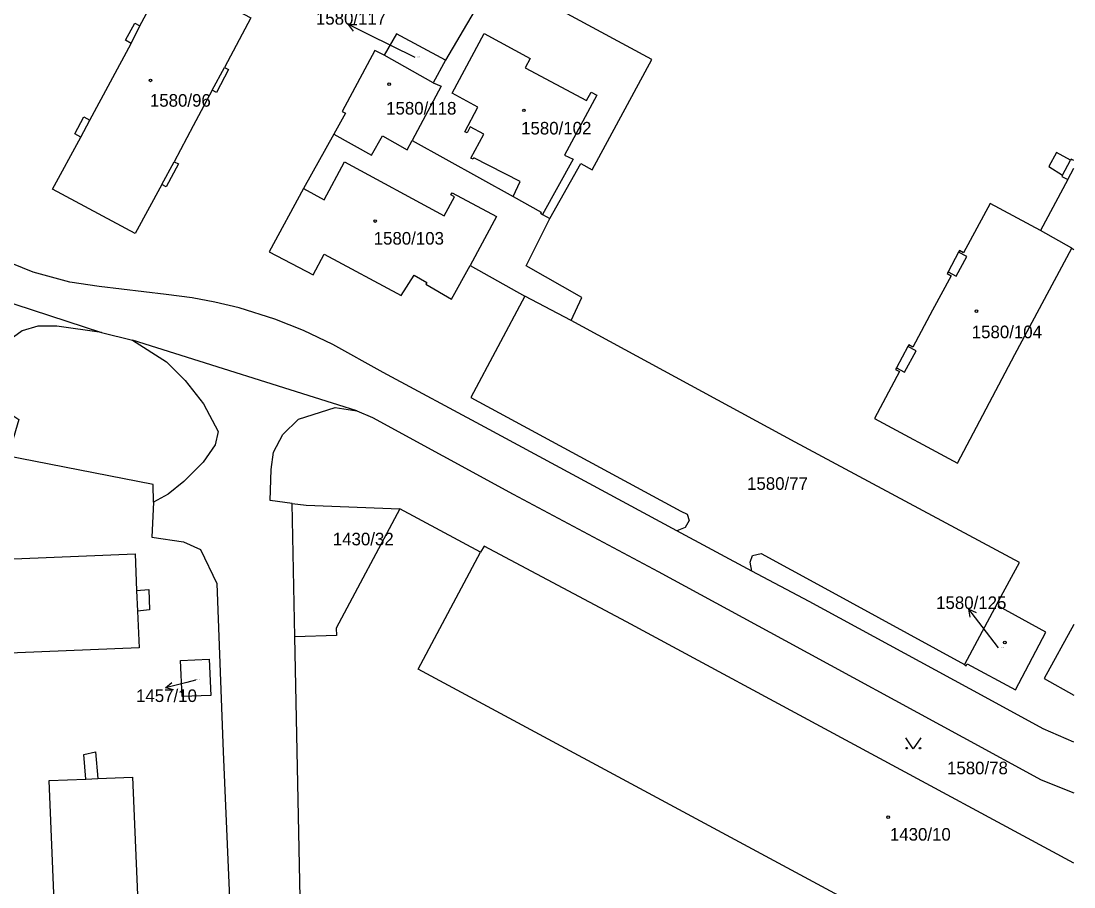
# Model space of a CAD drawing. Extents: x -736397 to -735924, y -1118983 to -1118245.
# Drawn here: x -736070.2 to -735928, y -1118454.8 to -1118338 of the extents above; entities that cross this region are included whole.
import ezdxf

# ---------------------------------------------------------------- set-up
doc = ezdxf.new("R2010")
doc.units = 0
for name, color, linetype in [('Vrstva 1', 7, 'Continuous'), ('Vrstva 16', 7, 'Continuous'), ('Vrstva 18', 7, 'Continuous'), ('Vrstva 19', 7, 'Continuous'), ('Vrstva 25', 7, 'Continuous'), ('Vrstva 4', 7, 'Continuous')]:
    doc.layers.add(name, color=color, linetype=linetype)

msp = doc.modelspace()

# ---------------------------------------------------------------- linework, layer by layer
at = {"layer": 'Vrstva 1'}
for p, q in [((-736014.55, -1118346.3), (-736021.15, -1118342.55)), ((-736012.85, -1118343.25), (-736014.55, -1118346.3)), ((-736027.93, -1118353.21), (-736032.05, -1118360.56)), ((-736017.37, -1118354.1), (-736003.75, -1118361.65)), ((-735928.88, -1118359.35), (-735932.57, -1118366.22)), ((-735999.77, -1118364.06), (-735998.8, -1118364.6)), ((-735928.33, -1118368.63), (-735932.57, -1118366.22)), ((-735943.62, -1118369.13), (-735945.03, -1118371.81)), ((-736009.55, -1118370.95), (-736002.16, -1118375.09)), ((-736081.16, -1118372.84), (-736059.31, -1118379.99)), ((-735995.92, -1118378.38), (-736002.16, -1118375.09)), ((-736059.31, -1118379.99), (-736055.13, -1118381.03)), ((-736024.84, -1118390.55), (-736055.13, -1118381.03)), ((-735950.45, -1118381.87), (-735951.99, -1118384.74)), ((-736033.2, -1118421.05), (-736033.57, -1118403.05)), ((-736008.14, -1118409.65), (-736019.04, -1118403.8)), ((-735971.52, -1118412.19), (-735981.63, -1118406.73)), ((-735938.42, -1118416.56), (-735942.8, -1118424.77))]:
    msp.add_line(p, q, dxfattribs=at)
for points in [[(-735981.63, -1118406.73), (-736007.57, -1118392.76), (-736021.29, -1118385.4), (-736028.1, -1118381.59), (-736032.04, -1118379.73), (-736035.9, -1118378.2), (-736040.7, -1118376.65), (-736044.01, -1118375.88), (-736047.06, -1118375.3), (-736050.57, -1118374.86), (-736059.63, -1118373.8), (-736063.58, -1118373.19), (-736068.55, -1118371.85), (-736072.64, -1118370.2), (-736076.44, -1118368.41), (-736088.36, -1118362.67), (-736110.12, -1118350.32), (-736124.12, -1118342.88), (-736126.16, -1118341.48), (-736136.25, -1118333.56), (-736143.63, -1118327.06), (-736151.23, -1118320.2)], [(-736054.14, -1118338.61), (-736050.34, -1118331.61), (-736039.16, -1118337.53), (-736042.72, -1118344.22)], [(-735998.8, -1118364.6), (-735994.62, -1118357.18), (-735993.05, -1118358.05), (-735985, -1118343.15), (-735999.87, -1118335.12), (-735998.28, -1118332.29), (-736000.23, -1118331.14), (-736003.3, -1118336.9), (-736007.84, -1118334.58), (-736009.02, -1118336.69), (-736012.85, -1118343.25)], [(-736055.28, -1118340.98), (-736056.07, -1118340.55), (-736054.82, -1118338.24), (-736054.14, -1118338.61)], [(-736060.88, -1118351.32), (-736058.09, -1118346.17), (-736055.28, -1118340.98)], [(-736012.85, -1118343.25), (-736019.5, -1118339.7), (-736021.15, -1118342.55)], [(-736021.15, -1118342.55), (-736022.39, -1118341.92), (-736026.83, -1118350.15), (-736026.35, -1118350.4), (-736027.93, -1118353.21)], [(-736042.72, -1118344.22), (-736042.15, -1118344.52), (-736043.8, -1118347.62), (-736044.37, -1118347.31)], [(-736014.55, -1118346.3), (-736013.45, -1118346.74), (-736017.37, -1118354.1)], [(-736044.37, -1118347.31), (-736046.93, -1118352.11), (-736049.5, -1118356.94)], [(-736062.11, -1118353.62), (-736062.91, -1118353.18), (-736061.7, -1118350.87), (-736060.88, -1118351.32)], [(-736051.15, -1118360.04), (-736054.75, -1118366.64), (-736065.9, -1118360.63), (-736062.11, -1118353.62)], [(-736027.93, -1118353.21), (-736022.86, -1118356.06), (-736021.39, -1118353.44), (-736018.03, -1118355.32), (-736017.37, -1118354.1)], [(-735928.5, -1118356.74), (-735930.39, -1118355.72), (-735931.43, -1118357.61), (-735929.58, -1118358.75)], [(-735928.04, -1118356.8), (-735928.42, -1118356.59), (-735928.5, -1118356.74)], [(-736049.5, -1118356.94), (-736048.93, -1118357.25), (-736050.58, -1118360.34), (-736051.15, -1118360.04)], [(-735929.58, -1118358.75), (-735929.67, -1118358.93), (-735928.88, -1118359.35)], [(-736032.05, -1118360.56), (-736036.68, -1118369.1), (-736030.75, -1118372.23), (-736029.23, -1118369.42), (-736018.86, -1118374.99), (-736017.09, -1118372.24), (-736015.39, -1118373.23), (-736015.53, -1118373.48), (-736012.05, -1118375.5), (-736009.55, -1118370.95)], [(-736003.75, -1118361.65), (-735999.97, -1118363.76), (-736000.05, -1118363.9), (-735999.77, -1118364.06)], [(-735932.57, -1118366.22), (-735939.34, -1118362.57), (-735942.93, -1118369.22), (-735943.5, -1118368.91), (-735943.62, -1118369.13)], [(-735995.92, -1118378.38), (-735994.45, -1118375.26), (-736001.99, -1118370.98), (-735998.8, -1118364.6)], [(-735951.99, -1118384.74), (-735952.12, -1118384.97), (-735951.57, -1118385.26), (-735954.98, -1118391.58), (-735943.77, -1118397.62), (-735936, -1118382.98), (-735928.33, -1118368.63)], [(-735928.33, -1118368.63), (-735928.04, -1118368.79)], [(-736052.29, -1118402.89), (-736052.32, -1118400.48), (-736090.36, -1118393.09), (-736118.86, -1118378.12), (-736124.09, -1118377.65), (-736210.35, -1118369.86)], [(-735945.03, -1118371.81), (-735945.15, -1118372.03), (-735944.6, -1118372.33), (-735947.11, -1118376.99), (-735949.78, -1118381.95), (-735950.33, -1118381.65), (-735950.45, -1118381.87)], [(-736002.16, -1118375.09), (-736009.45, -1118388.75), (-735981.08, -1118404.09), (-735980.26, -1118404.51), (-735979.97, -1118405.34), (-735980.5, -1118406.29), (-735981.63, -1118406.73)], [(-736059.31, -1118379.99), (-736065.33, -1118379.12), (-736067.91, -1118379.12), (-736070.03, -1118379.76), (-736071.67, -1118380.97), (-736072.98, -1118382.66), (-736073.71, -1118384.56), (-736073.92, -1118386.61), (-736073.5, -1118388.55), (-736072.34, -1118390.47), (-736070.47, -1118391.75), (-736071.45, -1118395.11), (-736088.43, -1118390.14)], [(-735938.42, -1118416.56), (-735935.38, -1118411.03), (-735965.68, -1118394.77), (-735995.92, -1118378.38)], [(-736055.13, -1118381.03), (-736050.54, -1118383.93), (-736048, -1118386.46), (-736045.54, -1118389.63), (-736043.55, -1118393.33), (-736043.97, -1118395.14), (-736045.58, -1118397.49), (-736048.17, -1118400.11), (-736050.29, -1118401.81), (-736052.29, -1118402.89)], [(-736033.57, -1118403.05), (-736036.53, -1118402.65), (-736036.38, -1118398.46), (-736036.07, -1118396.14), (-736034.82, -1118393.76), (-736032.71, -1118391.67), (-736027.76, -1118390.11), (-736024.84, -1118390.55)], [(-736024.84, -1118390.55), (-736022.72, -1118391.46), (-736003.72, -1118401.79), (-735984.18, -1118412.24), (-735967.03, -1118421.55), (-735943.02, -1118434.61), (-735932.48, -1118440.36), (-735928.04, -1118442.09)], [(-736052.29, -1118402.89), (-736052.52, -1118407.59), (-736048.25, -1118408.23), (-736045.95, -1118409.28), (-736043.72, -1118413.88), (-736042.87, -1118436.57), (-736038.55, -1118536.42)], [(-736033.57, -1118403.05), (-736031.67, -1118403.31), (-736019.04, -1118403.8)], [(-736019.04, -1118403.8), (-736027.62, -1118419.89), (-736027.57, -1118420.89), (-736033.2, -1118421.05)], [(-735928.04, -1118451.59), (-735988.45, -1118419.05), (-736007.65, -1118408.84), (-736008.14, -1118409.65)], [(-736054.44, -1118417.58), (-736054.24, -1118422.54), (-736096.98, -1118424.31), (-736097.43, -1118411.63), (-736054.76, -1118409.87), (-736054.56, -1118414.79)], [(-735928.04, -1118473.03), (-736016.57, -1118425.44), (-736008.14, -1118409.65)], [(-735971.52, -1118412.19), (-735971.74, -1118410.99), (-735971.44, -1118410.1), (-735970.28, -1118409.83), (-735962.16, -1118414.22), (-735942.8, -1118424.77)], [(-735928.04, -1118435.27), (-735932.17, -1118433.45), (-735940, -1118429.21), (-735963.76, -1118416.3), (-735971.52, -1118412.19)], [(-736054.56, -1118414.79), (-736052.93, -1118414.66), (-736052.82, -1118417.43), (-736054.44, -1118417.58)], [(-735942.8, -1118424.77), (-735942.57, -1118424.96), (-735942.43, -1118424.7), (-735935.94, -1118428.19), (-735931.81, -1118420.43), (-735938.21, -1118416.92), (-735938.11, -1118416.7), (-735938.42, -1118416.56)], [(-735928.04, -1118419.41), (-735932.06, -1118426.68), (-735928.04, -1118428.91)], [(-736022.3, -1118670.45), (-736022.74, -1118659.75), (-736029.23, -1118512.27), (-736032.47, -1118456.28), (-736033.2, -1118421.05)], [(-736044.55, -1118428.99), (-736048.4, -1118429.12), (-736048.66, -1118424.27), (-736044.76, -1118424.06), (-736044.55, -1118428.99)], [(-736061.43, -1118440.24), (-736061.69, -1118436.94), (-736060.13, -1118436.56), (-736059.79, -1118440.18)], [(-736064.7, -1118480.68), (-736066.37, -1118440.43), (-736061.43, -1118440.24)], [(-736059.79, -1118440.18), (-736055.12, -1118440), (-736053.39, -1118480.25), (-736056.21, -1118480.36)]]:
    msp.add_lwpolyline(points, dxfattribs=at)
at = {"layer": 'Vrstva 16'}
for points in [[(-736025.29, -1118339.34), (-736025.96, -1118338.45), (-736024.84, -1118338.44)], [(-736016.97, -1118342.87), (-736023.27, -1118339.77), (-736025.96, -1118338.45)], [(-735938.21, -1118422.56), (-735940.42, -1118419.68), (-735942.24, -1118417.3)], [(-735942.03, -1118418.4), (-735942.24, -1118417.3), (-735941.24, -1118417.79)], [(-736046.61, -1118426.89), (-736047.77, -1118427.2), (-736050.67, -1118427.96)], [(-736049.58, -1118428.19), (-736050.67, -1118427.96), (-736049.83, -1118427.22)]]:
    msp.add_lwpolyline(points, dxfattribs=at)
at = {"layer": 'Vrstva 25'}
msp.add_lwpolyline([(-735948.72, -1118434.68), (-735949.72, -1118436.18), (-735950.72, -1118434.68)], dxfattribs=at)
for centre in [(-735950.62, -1118436.08), (-735948.82, -1118436.08)]:
    msp.add_circle(centre, 0.1, dxfattribs=at)
for centre in [(-736052.7, -1118345.97), (-736020.48, -1118346.49), (-736002.28, -1118350.01), (-736022.35, -1118364.95), (-735941.21, -1118377.11), (-735937.36, -1118421.82), (-735953.12, -1118445.4)]:
    msp.add_ellipse(centre, major_axis=(0.18, 0), ratio=0.984808, dxfattribs=at)
at = {"layer": 'Vrstva 4'}
for p, q in [((-736055.28, -1118340.98), (-736054.14, -1118338.61)), ((-736044.37, -1118347.31), (-736042.72, -1118344.22)), ((-736062.11, -1118353.62), (-736060.88, -1118351.32)), ((-736051.15, -1118360.04), (-736049.5, -1118356.94)), ((-735929.58, -1118358.75), (-735928.5, -1118356.74)), ((-735928.88, -1118359.35), (-735928.04, -1118357.8)), ((-736054.56, -1118414.79), (-736054.44, -1118417.58)), ((-736061.43, -1118440.24), (-736059.79, -1118440.18))]:
    msp.add_line(p, q, dxfattribs=at)
for points in [[(-736003.75, -1118361.65), (-736002.78, -1118359.61), (-736009.04, -1118356.4), (-736009.14, -1118356.6), (-736009.44, -1118356.45), (-736007.71, -1118353.23), (-736009.52, -1118352.25), (-736009.95, -1118353.05), (-736010.26, -1118352.89), (-736008.49, -1118349.59), (-736011.99, -1118347.71), (-736007.67, -1118339.66), (-736001.42, -1118343), (-736002.1, -1118344.26), (-735993.83, -1118348.68), (-735993.22, -1118347.54), (-735992.45, -1118347.96), (-735996.79, -1118356.08), (-735995.62, -1118356.62), (-735999.77, -1118364.06)], [(-736032.05, -1118360.56), (-736029.23, -1118362.07), (-736026.49, -1118356.98), (-736013.04, -1118364.26), (-736011.65, -1118361.69), (-736012.13, -1118361.43), (-736011.98, -1118361.14), (-736006, -1118364.35), (-736009.55, -1118370.95)], [(-735945.03, -1118371.81), (-735943.94, -1118372.4), (-735942.51, -1118369.73), (-735943.62, -1118369.13)], [(-735951.99, -1118384.74), (-735950.89, -1118385.33), (-735949.35, -1118382.47), (-735950.45, -1118381.87)]]:
    msp.add_lwpolyline(points, dxfattribs=at)

# ---------------------------------------------------------------- texts
at = {"layer": 'Vrstva 16'}
for s, p in [('1580/117', (-736030.36, -1118338.45)), ('1580/125', (-735946.64, -1118417.3)), ('1457/10', (-736054.64, -1118429.85))]:
    msp.add_text(s, height=1.7, dxfattribs=at).set_placement(p)
at = {"layer": 'Vrstva 18'}
for s, height, p in [('1580/117', 0.1, (-736016.77, -1118342.87)), ('1580/77', 1.7, (-735972.16, -1118401.22)), ('1430/32', 1.7, (-736028.08, -1118408.71)), ('1457/10', 0.1, (-736046.61, -1118426.89)), ('1580/78', 1.7, (-735945.17, -1118439.6))]:
    msp.add_text(s, height=height, dxfattribs=at).set_placement(p)
at = {"layer": 'Vrstva 19'}
for s, height, p in [('1580/96', 1.7, (-736052.77, -1118349.52)), ('1580/118', 1.7, (-736020.88, -1118350.58)), ('1580/102', 1.7, (-736002.66, -1118353.27)), ('1580/103', 1.7, (-736022.56, -1118368.13)), ('1580/104', 1.7, (-735941.83, -1118380.76)), ('1580/125', 0.1, (-735937.98, -1118422.56)), ('1430/10', 1.7, (-735952.88, -1118448.56))]:
    msp.add_text(s, height=height, dxfattribs=at).set_placement(p)

doc.saveas('drawing.dxf')
